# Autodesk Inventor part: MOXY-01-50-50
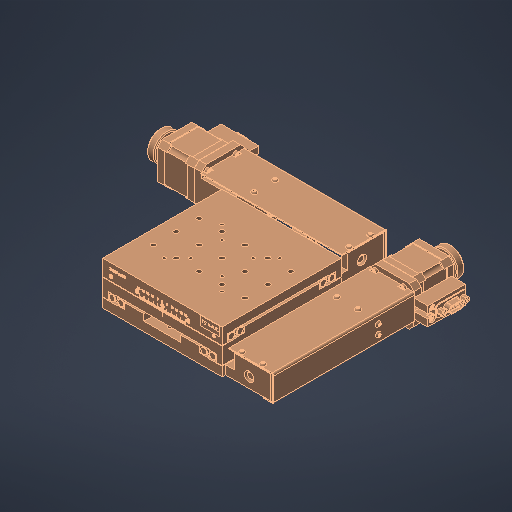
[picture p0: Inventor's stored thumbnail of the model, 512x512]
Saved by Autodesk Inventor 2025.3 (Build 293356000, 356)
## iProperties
Created: 2017-10
Part Number: MOXY-01-50-50
Project: COMMON
Material: Generic
Catalog Web Link: https://www.janelia.org/
Vendor: HHMI: JRC - JET
Document SubType Name: Modeling
Designer: sohna
Density: 1 g/cm^3
Appearance: Default
RuleStatus: InUse
AfterDocSave0: file://Part Number Cleaner
Title: Standard
Author: sohna
Revision Number: 0
LAB/DEPT: COMMON
REQUESTING SCIENTIST: COMMON
DESIGN DEPARTMENT: HHMI: JRC - ID&F
ALTERED ITEM PART NUMBER: N/A
ALTERED ITEM VENDOR: N/A
ALTERED ITEM DESCRIPTION: N/A
Part Number: 7SWA0350µç¶¯Ë«ÖáÆ½ÒÆÌ¨
Revision: ÈÎºÎ
Title: 7SWA0350µç¶¯Ë«ÖáÆ½ÒÆÌ¨.STEP
Description: STEP AP203
Sending System: SolidWorks 2014
Preprocessor: SwSTEP 2.0
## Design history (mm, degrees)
feature "Composite1"
body "Srf1"
